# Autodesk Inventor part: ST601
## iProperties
Created: 2006-02
Part Number: ST601
Material: -
Description: Goupille mécanindus, ISO 13337 - 4 x 22
Document SubType Name: Modeling
Standard: ISO 13337
Designer: Gilles GLEMAREC
Standard Revision: Première édition 1997-11-15
Standards Organization: ISO
Language: fr-FR
Size Designation: 4 x 22
Categories: <MemberInstance><Categories><Category DisplayName="Visserie" InternalName="e4da775c-781d-43d5-af7c-5136215cf5a6" Mnemonic="FSTN"><Category DisplayName="Goupille
Stock Number: ST601
Author: Gilles GLEMAREC
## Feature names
1. Corps [Revolution]
2. Coupe [Extrusion]
